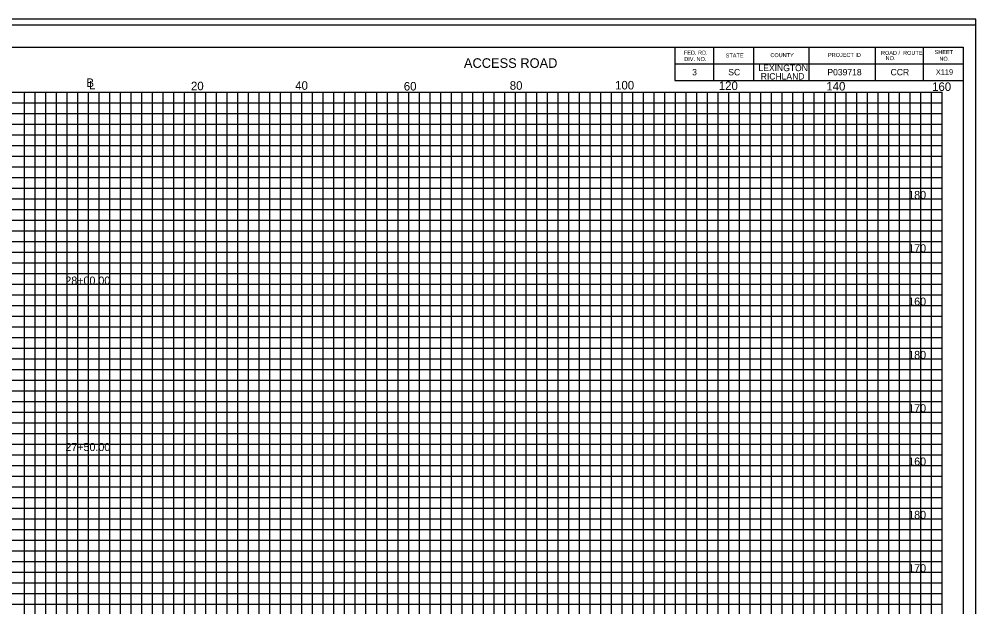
# Model space of a CAD drawing. Extents: x 967 to 1326, y 964 to 2864.
# Drawn here: x 1147 to 1326.3, y 2473.5 to 2583.7 of the extents above; entities that cross this region are included whole.
import ezdxf

# ---------------------------------------------------------------- set-up
doc = ezdxf.new("R2010")
doc.units = 0
for name, color, linetype in [('Default', 7, 'Continuous'), ('RD_EX_RW', 7, 'Continuous'), ('RD_PD_Final_TX', 7, 'Continuous'), ('RD_SHT_ShtClip', 7, 'Continuous'), ('RD_XS_TX_Elev_PR', 7, 'Continuous'), ('RD_XS_TX_Slope', 7, 'Continuous')]:
    doc.layers.add(name, color=color, linetype=linetype)

msp = doc.modelspace()

# ---------------------------------------------------------------- linework, layer by layer
at = {"layer": 'RD_EX_RW'}
for p, q in [((1000, 2570), (1320, 2570)), ((1150, 2400), (1150, 2570)), ((1160, 2400), (1160, 2570)), ((1170, 2400), (1170, 2570)), ((1180, 2400), (1180, 2570)), ((1190, 2400), (1190, 2570)), ((1200, 2400), (1200, 2570)), ((1210, 2400), (1210, 2570)), ((1220, 2400), (1220, 2570)), ((1230, 2400), (1230, 2570)), ((1240, 2400), (1240, 2570)), ((1250, 2400), (1250, 2570)), ((1260, 2400), (1260, 2570)), ((1270, 2400), (1270, 2570)), ((1280, 2400), (1280, 2570)), ((1290, 2400), (1290, 2570)), ((1300, 2400), (1300, 2570)), ((1310, 2400), (1310, 2570)), ((1320, 2400), (1320, 2570)), ((1000, 2560), (1320, 2560)), ((1000, 2550), (1320, 2550)), ((1000, 2540), (1320, 2540)), ((1000, 2530), (1320, 2530)), ((1000, 2520), (1320, 2520)), ((1000, 2510), (1320, 2510)), ((1000, 2500), (1320, 2500)), ((1000, 2490), (1320, 2490)), ((1000, 2480), (1320, 2480))]:
    msp.add_line(p, q, dxfattribs=at)
at = {"layer": 'RD_PD_Final_TX'}
for p, q in [((996.11, 2578.46), (1323.89, 2578.46)), ((1269.89, 2578.46), (1269.89, 2572.21)), ((1277.14, 2578.46), (1277.14, 2572.21)), ((1284.64, 2578.46), (1284.64, 2572.21)), ((1295, 2578.46), (1295, 2572.21)), ((1307.43, 2578.46), (1307.43, 2572.21)), ((1316.39, 2578.46), (1316.39, 2572.21)), ((1323.89, 2578.46), (1323.89, 2368.98)), ((1269.89, 2575.33), (1323.89, 2575.33)), ((1269.89, 2572.21), (1323.89, 2572.21))]:
    msp.add_line(p, q, dxfattribs=at)
at = {"layer": 'RD_SHT_ShtClip'}
for p, q in [((1148, 2400), (1148, 2570)), ((1152, 2400), (1152, 2570)), ((1154, 2400), (1154, 2570)), ((1156, 2400), (1156, 2570)), ((1158, 2400), (1158, 2570)), ((1162, 2400), (1162, 2570)), ((1164, 2400), (1164, 2570)), ((1166, 2400), (1166, 2570)), ((1168, 2400), (1168, 2570)), ((1172, 2400), (1172, 2570)), ((1174, 2400), (1174, 2570)), ((1176, 2400), (1176, 2570)), ((1178, 2400), (1178, 2570)), ((1182, 2400), (1182, 2570)), ((1184, 2400), (1184, 2570)), ((1186, 2400), (1186, 2570)), ((1188, 2400), (1188, 2570)), ((1192, 2400), (1192, 2570)), ((1194, 2400), (1194, 2570)), ((1196, 2400), (1196, 2570)), ((1198, 2400), (1198, 2570)), ((1202, 2400), (1202, 2570)), ((1204, 2400), (1204, 2570)), ((1206, 2400), (1206, 2570)), ((1208, 2400), (1208, 2570)), ((1212, 2400), (1212, 2570)), ((1214, 2400), (1214, 2570)), ((1216, 2400), (1216, 2570)), ((1218, 2400), (1218, 2570)), ((1222, 2400), (1222, 2570)), ((1224, 2400), (1224, 2570)), ((1226, 2400), (1226, 2570)), ((1228, 2400), (1228, 2570)), ((1232, 2400), (1232, 2570)), ((1234, 2400), (1234, 2570)), ((1236, 2400), (1236, 2570)), ((1238, 2400), (1238, 2570)), ((1242, 2400), (1242, 2570)), ((1244, 2400), (1244, 2570)), ((1246, 2400), (1246, 2570)), ((1248, 2400), (1248, 2570)), ((1252, 2400), (1252, 2570)), ((1254, 2400), (1254, 2570)), ((1256, 2400), (1256, 2570)), ((1258, 2400), (1258, 2570)), ((1262, 2400), (1262, 2570)), ((1264, 2400), (1264, 2570)), ((1266, 2400), (1266, 2570)), ((1268, 2400), (1268, 2570)), ((1272, 2400), (1272, 2570)), ((1274, 2400), (1274, 2570)), ((1276, 2400), (1276, 2570)), ((1278, 2400), (1278, 2570)), ((1282, 2400), (1282, 2570)), ((1284, 2400), (1284, 2570)), ((1286, 2400), (1286, 2570)), ((1288, 2400), (1288, 2570)), ((1292, 2400), (1292, 2570)), ((1294, 2400), (1294, 2570)), ((1296, 2400), (1296, 2570)), ((1298, 2400), (1298, 2570)), ((1302, 2400), (1302, 2570)), ((1304, 2400), (1304, 2570)), ((1306, 2400), (1306, 2570)), ((1308, 2400), (1308, 2570)), ((1312, 2400), (1312, 2570)), ((1314, 2400), (1314, 2570)), ((1316, 2400), (1316, 2570)), ((1318, 2400), (1318, 2570)), ((1000, 2568), (1320, 2568)), ((1000, 2566), (1320, 2566)), ((1000, 2564), (1320, 2564)), ((1000, 2562), (1320, 2562)), ((1000, 2558), (1320, 2558)), ((1000, 2556), (1320, 2556)), ((1000, 2554), (1320, 2554)), ((1000, 2552), (1320, 2552)), ((1000, 2548), (1320, 2548)), ((1000, 2546), (1320, 2546)), ((1000, 2544), (1320, 2544)), ((1000, 2542), (1320, 2542)), ((1000, 2538), (1320, 2538)), ((1000, 2536), (1320, 2536)), ((1000, 2534), (1320, 2534)), ((1000, 2532), (1320, 2532)), ((1000, 2528), (1320, 2528)), ((1000, 2526), (1320, 2526)), ((1000, 2524), (1320, 2524)), ((1000, 2522), (1320, 2522)), ((1000, 2518), (1320, 2518)), ((1000, 2516), (1320, 2516)), ((1000, 2514), (1320, 2514)), ((1000, 2512), (1320, 2512)), ((1000, 2508), (1320, 2508)), ((1000, 2506), (1320, 2506)), ((1000, 2504), (1320, 2504)), ((1000, 2502), (1320, 2502)), ((1000, 2498), (1320, 2498)), ((1000, 2496), (1320, 2496)), ((1000, 2494), (1320, 2494)), ((1000, 2492), (1320, 2492)), ((1000, 2488), (1320, 2488)), ((1000, 2486), (1320, 2486)), ((1000, 2484), (1320, 2484)), ((1000, 2482), (1320, 2482)), ((1000, 2478), (1320, 2478)), ((1000, 2476), (1320, 2476)), ((1000, 2474), (1320, 2474))]:
    msp.add_line(p, q, dxfattribs=at)
at = {"layer": 'RD_XS_TX_Elev_PR'}
for points in [[(967.41, 2363.72), (1326.28, 2363.72), (1326.28, 2583.72), (967.41, 2583.72)], [(988.52, 2364.84), (1326.28, 2364.84), (1326.28, 2582.6), (988.52, 2582.6)]]:
    msp.add_lwpolyline(points, close=True, dxfattribs=at)

# ---------------------------------------------------------------- texts
at = {"layer": 'Default'}
for s, height, p in [('X119', 1, (1318.79, 2573.3)), ('180', 1.5, (1313.61, 2550)), ('170', 1.5, (1313.61, 2540)), ('28+00.00', 1.5, (1155.66, 2533.94)), ('160', 1.5, (1313.61, 2530)), ('180', 1.5, (1313.61, 2520)), ('170', 1.5, (1313.61, 2510)), ('27+50.00', 1.5, (1155.66, 2502.72)), ('160', 1.5, (1313.61, 2500)), ('180', 1.5, (1313.61, 2490)), ('170', 1.5, (1313.61, 2480))]:
    msp.add_text(s, height=height, dxfattribs=at).set_placement(p)
at = {"layer": 'RD_XS_TX_Slope'}
msp.add_text('ACCESS ROAD', height=1.8, rotation=0, dxfattribs=at).set_placement((1230.35, 2574.58))
for s, height, p in [('FED. RD.', 0.75, (1271.58, 2577.05)), ('DIV. NO.', 0.75, (1271.64, 2575.86)), ('STATE', 0.75, (1279.41, 2576.53)), ('COUNTY', 0.75, (1287.78, 2576.59)), ('PROJECT ID', 0.75, (1298.58, 2576.63)), ('ROAD /  ROUTE', 0.75, (1308.51, 2577.01)), ('   NO.', 0.75, (1308.51, 2576.03)), ('SHEET', 0.75, (1318.56, 2577.16)), ('NO.', 0.75, (1319.45, 2575.91)), ('LEXINGTON', 1.2, (1285.54, 2573.96)), ('3', 1.2, (1273.12, 2573.17)), ('SC', 1.2, (1279.89, 2573.17)), ('RICHLAND', 1.2, (1285.97, 2572.39)), ('P039718', 1.2, (1298.46, 2573.17)), ('CCR', 1.2, (1310.31, 2573.17)), ('B', 1.6, (1159.61, 2570.99)), ('L', 1.6, (1160.12, 2570.54)), ('20', 1.6, (1179.2, 2570.38)), ('40', 1.6, (1198.74, 2570.47)), ('60', 1.6, (1219.08, 2570.33)), ('80', 1.6, (1238.94, 2570.47)), ('100', 1.6, (1258.67, 2570.53)), ('120', 1.6, (1278.11, 2570.43)), ('140', 1.6, (1298.26, 2570.34)), ('160', 1.6, (1318.08, 2570.25))]:
    msp.add_text(s, height=height, dxfattribs=at).set_placement(p)

doc.saveas('drawing.dxf')
